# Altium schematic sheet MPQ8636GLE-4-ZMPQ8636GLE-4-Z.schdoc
size 127 x 101 mm
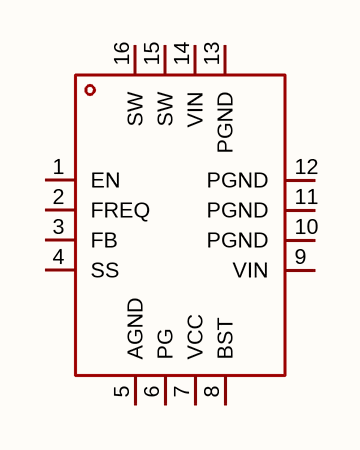
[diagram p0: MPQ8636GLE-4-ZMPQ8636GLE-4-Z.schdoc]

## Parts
U?  mpq8636gle-4-z  [QFN-16_L4.0-W3.0-P0.50-TL_MPQ8632GLE-8]  (value not drawn)

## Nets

Not connected (* = marked no-connect by the designer): U? 1(EN) 2(FREQ) 3(FB) 4(SS) 5(AGND) 6(PG) 7(VCC) 8(BST) 9(VIN) 10(PGND) 11(PGND) 12(PGND) 13(PGND) 14(VIN) 15(SW) 16(SW)

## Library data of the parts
U? = mpq8636gle-4-z: 功能类型:降压型;工作电压:4.5V~18V;输出电压:611mV~13V;输出电流:4A;输出类型:可调;; Manufacturer: MPS(芯源); AddInBom: yes; Function: 降压型; Output Current: 4A; Frequency - Switching: 200kHz~1MHz; Synchronous Rectifier: 是; Number of Outputs: 1; Topology: 降压式; Quiescent Current: 860uA; Switch tube (built-in/external): 内置; Output Type: 可调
